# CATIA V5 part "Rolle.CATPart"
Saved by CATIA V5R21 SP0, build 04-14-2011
Part number: Rolle
Bounding box of the stored display mesh (mm): x 144.45 to 163, y 0 to 356.816, z -764.177 to 0
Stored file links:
  C:\Users\Home\Desktop\Rollkurve_test_3\Rolle.CATPart

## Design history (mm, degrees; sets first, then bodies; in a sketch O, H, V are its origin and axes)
AxisSystem1: origin (144.45, 324.8165, -732.2342), X (1, 0, 0), Y (0, 1, 0), Z (0, 0, 1)
Set1
  Sketch1 on Plane1, origin (149.7, 0, 0), H (0, 1, 0), V (0, 0, 1)
    circle A1 centre (324.8165, -732.2342) radius 32
    point P1 (324.8165, -732.2342)
    reference projected point E1 (324.8165, -732.2342) from axis of face of Solid1
    point P2 (324.8165, -732.2342)
    radius A1 = 32
    coincidence: P1 E1, P2 P1
  Point1: type Center, Curve edge [face of Solid2 | face of Solid2]
  Point2: (5.25, 0, 0), relative to vertex [YZ plane of AxisSystem1 | ZX plane of AxisSystem1 | XY plane of AxisSystem1], in AxisSystem1
  Point3: (8.5, 0, 0), relative to Point2, in AxisSystem1
  Plane1: type OffsetPt, RefPlane YZ plane of AxisSystem1, RefPoint Point2
  Plane2: type OffsetPt, RefPlane YZ plane of AxisSystem1, RefPoint Point3
  Point4: (0, 32, 0), relative to Sketch1.P2, in AxisSystem1
Body1 (main body)
Body2 "Teil_1"
  Solid1: solid without history
  Sketch2 on face of Solid1, origin (155.5, 0, 0), H (0, -1, 0), V (0, 0, 1)
    projected circle E1 centre (-324.8165, -732.2342) radius 28.4 from edge [face of Solid1 | face of Solid1]
    projected circle E2 centre (-324.8165, -732.2342) radius 8 from edge [face of Solid1 | face of Solid1]
    projected circle E3 centre (-331.1669, -723.8722) radius 1.45 from edge [face of Solid1 | face of Solid1]
    projected circle E4 centre (-318.4661, -740.5961) radius 1.7 from edge [face of Solid1 | face of Solid1]
    projected circle E5 centre (-335.2334, -733.5528) radius 1.7 from edge [face of Solid1 | face of Solid1]
    projected circle E6 centre (-320.75, -722.5536) radius 1.7 from edge [face of Solid1 | face of Solid1]
    projected circle E7 centre (-314.3996, -730.9155) radius 1.45 from edge [face of Solid1 | face of Solid1]
    projected circle E8 centre (-328.8829, -741.9148) radius 1.45 from edge [face of Solid1 | face of Solid1]
  Pad1: profile Sketch2, direction (-1, 0, 0), up to face of Solid2
  DatumCurve1
  Sketch3 on end face of Pad1, origin (144.45, 0, 0), H (0, -1, 0), V (0, 0, 1)
    circle A1 centre (-324.8165, -732.2342) radius 32
    point P1 (-324.8165, -732.2342)
    reference projected point E1 (-324.8165, -732.2342) from edge of DatumCurve1
    radius A1 = 32
    coincidence: P1 E1
  Pad2: profile Sketch3, direction (1, 0, 0), length 4, opposite side length -2
  Fillet1: radius 1, on edge [end face of Pad2 | face of Pad2 from Sketch3.A1]; edge [face of Pad2 from Sketch3.A1 | start face of Pad2]
Body3 "Teil_2"
Body4 "Teil_3"
  Solid2 "Volumen.1": solid without history
Body5 "Teil_4"
  Solid3 "Volumen.1": solid without history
